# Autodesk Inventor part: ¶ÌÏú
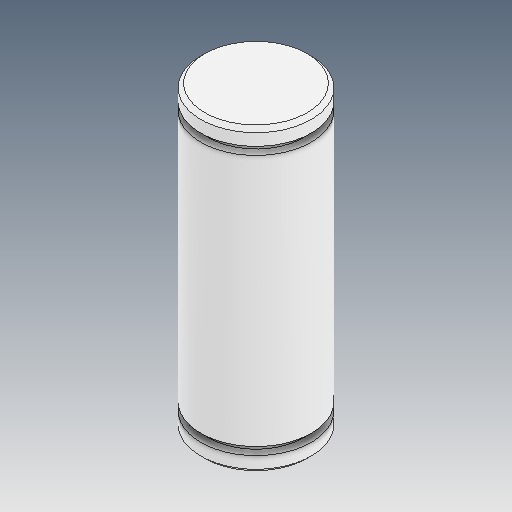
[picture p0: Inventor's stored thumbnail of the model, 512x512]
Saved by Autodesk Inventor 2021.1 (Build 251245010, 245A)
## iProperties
Created: 2021-05
Part Number: ¶ÌÏú
Material: Ogólny
Document SubType Name: Modeling
Designer: user
Density: 1 g/cm^3
Appearance: Domyślna
Author: user
Revision Number: ÈÎºÎ
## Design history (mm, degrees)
feature "ÊäÈë1"
node "Bryła1"
